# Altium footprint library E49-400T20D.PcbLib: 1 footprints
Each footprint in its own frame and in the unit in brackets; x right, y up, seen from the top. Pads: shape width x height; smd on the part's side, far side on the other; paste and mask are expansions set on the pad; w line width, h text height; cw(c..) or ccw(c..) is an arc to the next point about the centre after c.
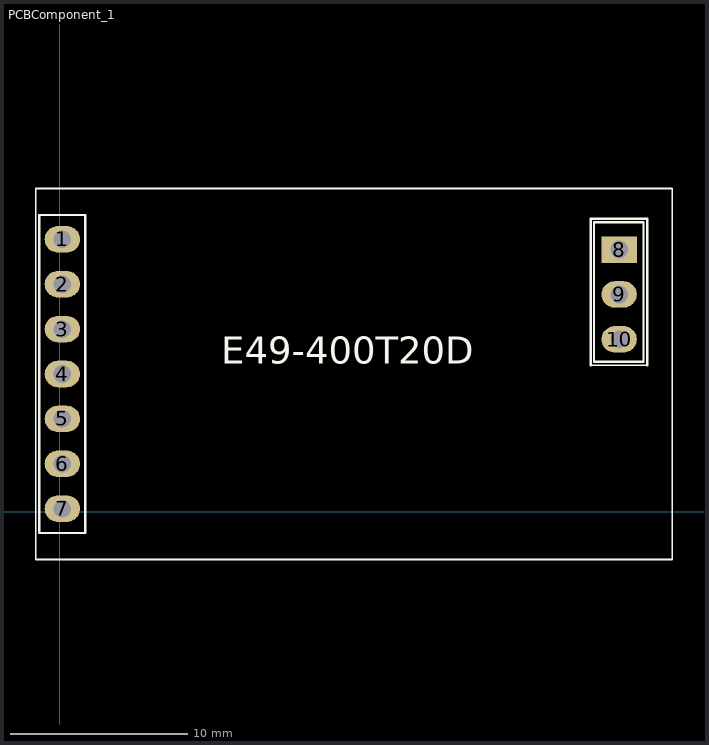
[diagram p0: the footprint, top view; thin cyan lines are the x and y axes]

## PCBComponent_1 [mm]
pads (10):
  oval 2x1.5 hole 1: 1(0.15,15.42) 2(0.15,12.88) 3(0.15,10.34) 4(0.15,7.8) 5(0.15,5.26) 6(0.15,2.72) 7(0.15,0.18) 9(31.65,12.3) 10(31.65,9.76)
  rect 2x1.5 hole 1: 8(31.65,14.84)
Top Layer:
  lines w0.3: 0.15,10.34 0.372,10.562
Top Overlay:
  lines w0.1: 30.05,8.29 33.24,8.29 ; -1.35,-2.7 34.65,-2.7 34.65,18.3 -1.35,18.3 -1.35,-2.7
  lines w0.127: 30.05,8.29 30.05,16.58 33.24,16.58 33.24,8.29 ; -1.15,-1.2 -1.15,16.8 1.45,16.8 1.45,-1.2 -1.15,-1.2 ; 30.23,8.49 33.03,8.49 33.03,16.08 33.03,16.39 30.23,16.39 30.23,16.08 30.23,8.49
  text "E49-400T20D" at 9.144,8.382 h1.52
